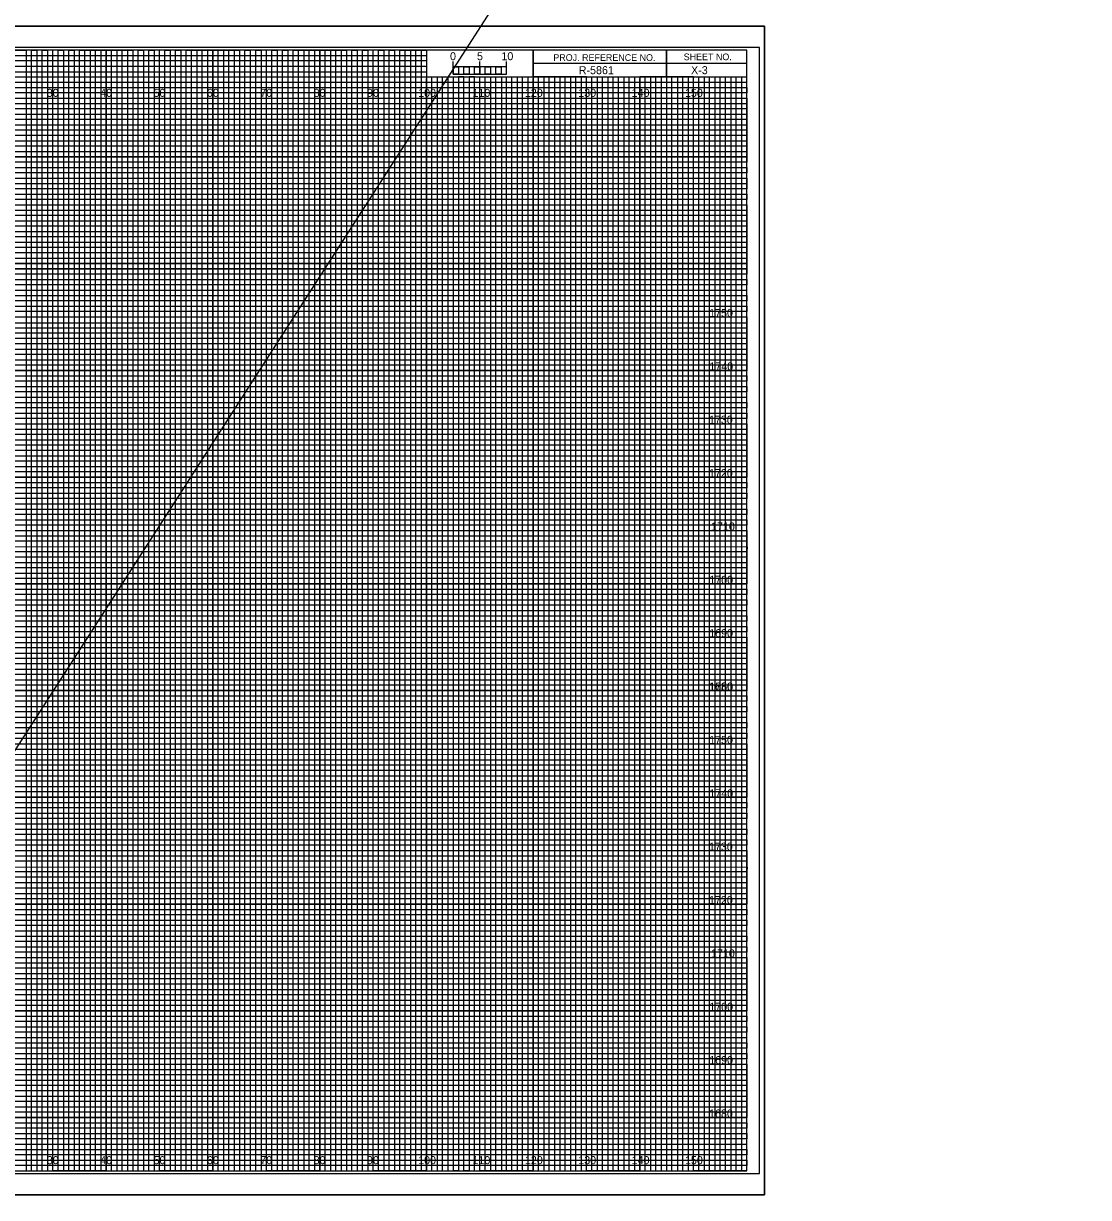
# Model space of a CAD drawing. Extents: x -419 to 4739, y -630 to 13534.
# Drawn here: x 184.5 to 384, y 435 to 655 of the extents above; entities that cross this region are included whole.
import ezdxf

# ---------------------------------------------------------------- set-up
doc = ezdxf.new("R2010")
doc.units = 0
for name, color, linetype in [('Old_Level_1', 7, 'Continuous'), ('Old_Level_62', 7, 'Continuous'), ('Pattern 1', 7, 'Continuous'), ('Pattern 18', 7, 'Continuous'), ('Pattern 4', 7, 'Continuous'), ('Pattern 5', 7, 'Continuous'), ('Prop Dimension', 7, 'Continuous'), ('Prop Horizontal Alignment', 7, 'Continuous'), ('Prop PHM Label Text', 7, 'Continuous'), ('Prop PHM Label Text White', 7, 'Continuous'), ('Prop PHM Roadway Shape', 7, 'Continuous'), ('Raster_Level_0', 7, 'Continuous'), ('Scratch_Level_0', 7, 'Continuous'), ('Scratch_Level_3', 7, 'Continuous'), ('Scratch_Level_5', 7, 'Continuous')]:
    doc.layers.add(name, color=color, linetype=linetype)

msp = doc.modelspace()

# ---------------------------------------------------------------- linework, layer by layer
at = {"layer": 'Old_Level_62'}
for p, q in [((305, 650), (305, 645)), ((305, 645), (305, 650)), ((280, 647.5), (280, 645)), ((320, 647.49), (280, 647.49)), ((280, 645), (320, 645))]:
    msp.add_line(p, q, dxfattribs=at)
for points in [[(320, 650), (0, 650), (0, 440), (320, 440)], [(280, 650), (260, 650), (260, 645.03), (280, 645.03)], [(320, 650), (280, 650), (280, 645), (320, 645)]]:
    msp.add_lwpolyline(points, close=True, dxfattribs=at)
at = {"layer": 'Pattern 18'}
msp.add_line((-419.01, -416.83), (1573.75, 2680.65), dxfattribs=at)
for points in [[(-13.4, 435.5), (323.3, 435.5), (323.3, 654.5), (-13.4, 654.5)], [(-13.4, 654.5), (323.3, 654.5), (323.3, 435.5), (-13.4, 435.5)]]:
    msp.add_lwpolyline(points, close=True, dxfattribs=at)
at = {"layer": 'Pattern 4'}
for p, q in [((0, 649), (260, 649)), ((260, 649), (260, 647.98)), ((260, 647.98), (0, 647.98)), ((0, 647), (260, 647)), ((260, 647), (260, 645.89)), ((260, 645.89), (0, 645.89)), ((0, 644), (320, 644))]:
    msp.add_line(p, q, dxfattribs=at)
for points in [[(0, 643), (270, 643), (320, 643), (320, 642), (0, 642)], [(0, 641), (320, 641), (320, 639), (0, 639)], [(0, 638), (320, 638), (320, 637), (0, 636.98)], [(0, 636), (320, 636), (320, 634), (0, 634)], [(0, 633), (320, 633), (320, 632), (0, 632)], [(0, 631), (320, 631), (320, 629), (0, 629)], [(0, 628), (320, 628), (320, 627), (0, 627)], [(0, 626), (320, 626), (320, 624), (0, 624)], [(0, 623), (320, 623), (320, 622), (0, 622)], [(0, 621), (320, 621), (320, 619), (0, 619)], [(0, 618), (320, 618), (320, 617), (0, 617)], [(0, 616), (320, 616), (320, 613.95), (320, 613), (320, 612), (0, 612)], [(0, 614), (320, 614), (320, 613), (0, 613)], [(0, 611), (320, 611), (320, 609), (0, 609.03)], [(0, 609.03), (320, 609), (320, 608), (0, 608)], [(0, 607), (320, 607), (320, 606), (0, 606)], [(0, 604), (320, 604), (320, 603), (0, 603)], [(0, 602), (320, 602), (320, 601), (0, 601)], [(-0.07, 598.89), (320, 598.89), (320, 597.88), (-0.07, 597.88)], [(0, 597), (320, 597), (320, 596), (0, 596)], [(0, 594), (320, 594), (320, 593), (0, 593)], [(0, 592), (320, 592), (320, 591), (0, 591)], [(0, 589), (320, 589), (320, 588), (0, 588)], [(0, 587), (320, 587), (320, 586), (0, 586)], [(0, 584), (320, 584), (320, 583), (0, 583)], [(0, 582), (320, 582), (320, 581), (0, 581)], [(0, 579), (320, 579), (319.99, 577.98), (0, 578)], [(0, 577), (320, 577), (320, 576), (0, 576)], [(0, 574), (320, 574), (320, 573), (0, 573)], [(0, 572), (320, 572), (320, 571), (0, 571)], [(0, 569), (320, 569), (320, 568), (0, 568)], [(0, 567), (320, 567), (320, 566), (0, 566)], [(0, 564), (320, 564), (320, 563), (0, 563)], [(0, 562), (320, 562), (320, 561), (0, 561)], [(0, 559), (320, 559), (320, 558), (0, 558)], [(0, 556.99), (320.07, 556.91), (320, 556), (0, 556)], [(0, 554), (320, 554), (320, 553), (0, 553)], [(0, 552), (320, 552), (320, 551), (0, 551)], [(0, 549), (320, 549), (320, 548), (0, 548)], [(0, 547), (320, 547), (320, 546), (0, 546)], [(0, 544), (320, 544), (320, 543), (0, 543)], [(0, 542), (320, 542), (320, 541), (0, 541)], [(0, 539), (320, 539), (320, 538), (0, 538)], [(0, 537), (320, 537), (320, 536), (0, 536)], [(0, 534), (320, 534), (320, 533), (0, 533)], [(0, 532), (320, 532), (320, 531), (0, 531)], [(0, 529), (320, 529), (320, 528), (0, 528)], [(0, 527), (320, 527), (320, 526), (0, 526)], [(0, 524), (320, 524), (320, 523), (0, 523)], [(0, 522), (320, 522), (320, 521), (0, 521)], [(0, 519), (320, 519), (319.99, 517.98), (0, 518)], [(0, 517), (320, 517), (320, 516), (0, 516)], [(0, 514), (320, 514), (320, 513), (0, 513)], [(0, 512), (320, 512), (320, 511), (0, 511)], [(0, 509), (320, 509), (320, 508), (0, 508)], [(0, 507), (320, 507), (320, 506), (0, 506)], [(0, 504), (320, 504), (320, 503), (0, 503)], [(0, 502), (320, 502), (320, 501), (0, 501)], [(0, 499), (320, 499), (320, 498), (0, 498)], [(0, 496.99), (320.07, 496.91), (320, 496), (0, 496)], [(0, 494), (320, 494), (320, 493), (0, 493)], [(0, 492), (320, 492), (320, 491), (0, 491)], [(0, 489), (320, 489), (320, 488), (0, 488)], [(0, 487), (320, 487), (320, 486), (0, 486)], [(0, 484), (320, 484), (320, 483), (0, 483)], [(0, 482), (320, 482), (320, 481), (0, 481)], [(0, 479), (320, 479), (320, 478), (0, 478)], [(0, 477), (320, 477), (320, 476), (0, 476)], [(0, 474), (320, 474), (320, 473), (0, 473)], [(0, 472), (320, 472), (320, 471), (0, 471)], [(0, 469), (320, 469), (320, 468), (0, 468)], [(0, 467), (320, 467), (320, 466), (0, 466)], [(0, 464), (320, 464), (320, 463), (0, 463)], [(0, 462), (320, 462), (320, 461), (0, 461)], [(0, 459), (320, 459), (320, 458), (0, 458)], [(0, 457), (320, 457), (320, 456), (0, 456)], [(0, 454), (320, 454), (320, 453), (0, 453)], [(0, 452), (320, 452), (320, 451), (0, 451)], [(0, 449), (320, 449), (320, 448), (0, 448)], [(0, 447), (320, 447), (320, 446), (0, 446)], [(0, 444), (320, 444), (320, 443), (0, 443)], [(0, 442), (320, 442), (320, 441), (0, 441)]]:
    msp.add_lwpolyline(points, dxfattribs=at)
at = {"layer": 'Pattern 5'}
for p, q in [((323.3, 654.5), (-13.4, 654.5)), ((-13.4, 435.5), (323.3, 435.5))]:
    msp.add_line(p, q, dxfattribs=at)
at = {"layer": 'Prop Dimension'}
for p, q in [((267, 645), (266.01, 645)), ((266.01, 645), (266.01, 440)), ((267, 440), (267, 645)), ((269, 645), (268, 645)), ((268, 645), (268, 440)), ((269, 440), (269, 645)), ((266.01, 440), (265, 440)), ((268, 440), (267, 440))]:
    msp.add_line(p, q, dxfattribs=at)
for points in [[(185, 440), (186, 440), (186, 650), (187, 650), (187, 440)], [(187, 440), (188, 440), (188, 650), (189, 650), (189, 440)], [(190, 440), (191, 440), (191, 650), (192, 650), (192, 440)], [(192, 440), (193, 440), (193, 650), (194, 650), (194, 440)], [(195, 440), (196, 440), (196, 650), (197, 650), (197, 440)], [(197, 440), (198, 440), (198, 650), (199, 650), (199, 440)], [(200, 440), (201, 440), (201, 650), (202, 650), (202, 440)], [(202, 440), (203, 440), (203, 650), (204, 650), (204, 440)], [(205, 440), (206, 440), (206, 650), (207, 650), (207, 440)], [(207, 440), (208, 440), (208, 650), (209, 650), (209, 440)], [(210, 440), (211, 440), (211, 650), (212, 650), (212, 440)], [(212, 440), (213, 440), (213, 650), (214, 650), (214, 440)], [(215, 440), (216, 440), (216, 650), (217, 650), (217, 440)], [(217, 440), (218, 440), (218, 650), (219, 650), (219, 440)], [(220, 440), (221, 440), (221, 650), (222, 650), (222, 440)], [(222, 440), (223, 440), (223, 650), (224, 650), (224, 440)], [(225, 440), (226, 440), (226, 650), (227, 650), (227, 440)], [(227, 440), (228, 440), (228, 650), (229, 650), (229, 440)], [(230, 440), (231, 440), (231, 650), (232, 650), (232, 440)], [(232, 440), (233, 440), (233, 650), (234, 650), (234, 440)], [(235, 440), (236, 440), (236, 650), (237, 650), (237, 440)], [(237, 440), (238, 440), (238, 650), (239, 650), (239, 440)], [(240, 440), (241, 440), (241, 650), (242, 650), (242, 440)], [(242, 440), (243, 440), (243, 650), (244, 650), (244, 440)], [(245, 440), (246, 440), (246, 650), (247, 650), (247, 440)], [(247, 440), (248, 440), (248, 650), (249, 650), (249, 440)], [(250, 440), (251, 440), (251, 650), (252, 650), (252, 440)], [(252, 440), (253, 440), (253, 650), (254, 650), (254, 440)], [(255, 440), (256, 440), (256, 650), (257, 650), (257, 440)], [(257, 440), (258, 440), (258, 650), (259, 650), (259, 440)], [(260, 440), (261, 440), (261, 645), (262.02, 645), (262.02, 440)], [(262, 440), (263, 440), (263, 645), (263.99, 645), (263.99, 440)], [(270, 440), (270.98, 440), (270.98, 645), (272, 645), (272, 440)], [(272, 440), (273, 440), (273, 645), (274.05, 645), (274.05, 440)], [(275, 440), (276, 440), (276, 645), (277, 645), (277, 440)], [(277, 440), (278, 440), (278, 645), (279, 645), (279, 440)], [(280, 440), (281, 440), (281, 645), (282, 645), (282, 440)], [(282, 440), (283, 440), (283, 645), (284, 645), (284, 440)], [(285, 440), (286, 440), (286, 645), (287, 645), (287, 440)], [(287, 440), (288, 440), (288, 645), (289, 645), (289, 440)], [(290, 440), (291, 440), (291, 645), (292, 645), (292, 440)], [(292, 440), (293, 440), (293, 645), (294, 645), (294, 440)], [(295, 440), (296, 440), (296, 645), (297, 645), (297, 440)], [(297, 440), (298, 440), (298, 645), (299, 645), (299, 440)], [(300, 440), (301, 440), (301, 645), (302, 645), (302, 440)], [(302, 440), (303, 440), (303, 645), (304, 645), (304, 440)], [(305, 440), (306, 440), (306, 645), (307, 645), (307, 440)], [(307, 440), (308, 440), (308, 645), (309, 645), (309, 440)], [(310, 440), (311, 440), (311, 645), (312, 645), (312, 440)], [(312, 440), (313, 440), (313, 645), (314, 645), (314, 440)], [(315, 440), (316, 440), (316, 645), (317, 645), (317, 440)], [(317, 440), (318, 440), (318, 645), (319, 645), (319, 440)]]:
    msp.add_lwpolyline(points, dxfattribs=at)
at = {"layer": 'Prop Horizontal Alignment'}
for points in [[(175, 650), (185, 650), (185, 440), (195, 440), (195, 650), (205, 650), (205, 440), (215, 440), (215, 650), (225, 650), (225, 440), (235, 440), (235, 650), (245, 650), (245, 440), (255, 440), (255, 650), (259.93, 650), (260, 650), (260, 645), (264.99, 645), (264.99, 440), (275, 440), (275, 645), (285, 645), (285, 440), (295, 440), (295, 645), (305, 645), (305, 440), (315, 440), (315, 645)], [(0, 645), (275, 645)], [(0, 625), (320, 625), (320, 635), (0, 635)], [(0, 605), (320, 605), (320, 615), (0, 615)], [(0, 585), (320, 585), (320, 595), (0, 595)], [(0, 565), (320, 565), (320, 575), (0, 575)], [(0, 545), (320, 545), (320, 555), (0, 555)], [(0, 525), (320, 525), (320, 535), (0, 535)], [(0, 505), (320, 505), (320, 515), (0, 515)], [(0, 485), (320, 485), (320, 495), (0, 495)], [(0, 465), (320, 465), (320, 475), (0, 475)], [(0, 445), (320, 445), (320, 455), (0, 455)]]:
    msp.add_lwpolyline(points, dxfattribs=at)
at = {"layer": 'Prop PHM Label Text'}
for p, q in [((265, 645.49), (265, 647.9)), ((265, 646.9), (265, 647.9)), ((270, 645.49), (270, 647.9)), ((275, 645.49), (275, 647.9)), ((275, 646.9), (275, 647.9))]:
    msp.add_line(p, q, dxfattribs=at)
for points in [[(275, 646.9), (265, 646.9), (265, 645.49), (275, 645.49)], [(265, 646.9), (266, 646.9), (266, 645.49), (265, 645.49)], [(267, 646.9), (268, 646.9), (268, 645.49), (267, 645.49)], [(269, 646.9), (270, 646.9), (270, 645.49), (269, 645.49)], [(271, 646.9), (272, 646.9), (272, 645.49), (271, 645.49)], [(273, 646.9), (274, 646.9), (274, 645.49), (273, 645.49)]]:
    msp.add_lwpolyline(points, close=True, dxfattribs=at)
at = {"layer": 'Scratch_Level_0'}
for p, q in [((190, 440), (190, 650)), ((200, 440), (200, 650)), ((210, 440), (210, 650)), ((220, 440), (220, 650)), ((230, 440), (230, 650)), ((240, 440), (240, 650)), ((250, 440), (250, 650)), ((260, 440), (260, 644.69)), ((270, 440), (270, 644.69)), ((280, 440), (280, 644.69)), ((290, 440), (290, 644.69)), ((300, 440), (300, 644.69)), ((310, 440), (310, 644.69)), ((0, 640), (320, 640)), ((0, 630), (320, 630)), ((0, 620), (320, 620)), ((0, 610), (320, 610)), ((0, 600), (320, 600)), ((0, 590), (320, 590)), ((0, 580), (320, 580)), ((0, 570), (320, 570)), ((0, 560), (320, 560)), ((0, 550), (320, 550)), ((0, 540), (320, 540)), ((0, 530), (320, 530)), ((0, 520), (320, 520)), ((0, 510), (320, 510)), ((0, 500), (320, 500)), ((0, 490), (320, 490)), ((0, 480), (320, 480)), ((0, 470), (320, 470)), ((0, 460), (320, 460)), ((0, 450), (320, 450))]:
    msp.add_line(p, q, dxfattribs=at)
at = {"layer": 'Scratch_Level_3'}
for p, q in [((190, 650), (180, 650)), ((190, 440), (190, 650)), ((210, 650), (200, 650)), ((200, 650), (200, 440)), ((210, 440), (210, 650)), ((230, 650), (220, 650)), ((220, 650), (220, 440)), ((230, 440), (230, 650)), ((250, 650), (240, 650)), ((240, 650), (240, 440)), ((250, 440), (250, 650)), ((260, 650), (260, 440)), ((270, 440), (270, 645)), ((290, 645), (280, 645)), ((280, 645), (280, 440)), ((290, 440), (290, 645)), ((310, 645), (300, 645)), ((300, 645), (300, 440)), ((310, 440), (310, 645)), ((200, 440), (190, 440)), ((220, 440), (210, 440)), ((240, 440), (230, 440)), ((260, 440), (250, 440)), ((280, 440), (270, 440)), ((300, 440), (290, 440)), ((320, 440), (310, 440)), ((320, 440), (320, 440))]:
    msp.add_line(p, q, dxfattribs=at)
for points in [[(0, 640), (320, 640), (320, 630), (0, 630)], [(0, 620), (320, 620), (320, 610), (0, 610)], [(0, 600), (320, 600), (320, 590), (0, 590)], [(0, 580), (320, 580), (320, 570), (0, 570)], [(0, 560), (320, 560), (320, 550), (0, 550)], [(0, 540), (320, 540), (320, 530), (0, 530)], [(0, 520), (320, 520), (320, 510), (0, 510)], [(0, 500), (320, 500), (320, 490), (0, 490)], [(0, 480), (320, 480), (320, 470), (0, 470)], [(0, 460), (320, 460), (320, 450), (0, 450)]]:
    msp.add_lwpolyline(points, dxfattribs=at)
at = {"layer": 'Scratch_Level_5'}
msp.add_lwpolyline([(-10.8, 439.5), (322.4, 439.5), (322.4, 650.5), (-10.8, 650.5)], close=True, dxfattribs=at)

# ---------------------------------------------------------------- texts
at = {"layer": 'Old_Level_1'}
for s, p in [('5', (269.47, 648.12)), ('10', (274.04, 648.12))]:
    msp.add_text(s, height=1.5, dxfattribs=at).set_placement(p)
at = {"layer": 'Old_Level_62'}
for s, p in [('PROJ. REFERENCE NO.', (283.77, 647.99)), ('SHEET NO.', (308.19, 648.12))]:
    msp.add_text(s, height=1.25, dxfattribs=at).set_placement(p)
at = {"layer": 'Pattern 1'}
for s, p in [('1750', (312.96, 600)), ('1740', (313, 590)), ('1730', (312.92, 580)), ('1720', (312.93, 570)), ('1710', (313.31, 560)), ('1700', (312.98, 550)), ('1690', (312.97, 540)), ('1680', (312.95, 530)), ('1760', (313, 530)), ('1750', (312.96, 520)), ('1740', (313, 510)), ('1730', (312.92, 500)), ('1720', (312.93, 490)), ('1710', (313.31, 480)), ('1700', (312.98, 470)), ('1690', (312.97, 460)), ('1680', (312.95, 450))]:
    msp.add_text(s, height=1.5, dxfattribs=at).set_placement(p)
at = {"layer": 'Prop PHM Label Text'}
msp.add_text('0', height=1.5, dxfattribs=at).set_placement((264.41, 648.12))
at = {"layer": 'Prop PHM Label Text White'}
msp.add_text('X-3', height=1.5, dxfattribs=at).set_placement((309.57, 645.5))
at = {"layer": 'Prop PHM Roadway Shape'}
msp.add_text('R-5861', height=1.5, dxfattribs=at).set_placement((288.53, 645.5))
at = {"layer": 'Raster_Level_0'}
for s, p in [('30', (188.86, 641.25)), ('40', (198.86, 641.25)), ('50', (208.86, 641.25)), ('60', (218.86, 641.25)), ('70', (228.86, 641.25)), ('80', (238.86, 641.25)), ('90', (248.86, 641.25)), ('100', (258.44, 641.25)), ('110', (268.62, 641.25)), ('120', (278.44, 641.25)), ('130', (288.44, 641.25)), ('140', (298.44, 641.25)), ('150', (308.44, 641.25)), ('30', (188.86, 441.25)), ('40', (198.86, 441.25)), ('50', (208.86, 441.25)), ('60', (218.86, 441.25)), ('70', (228.86, 441.25)), ('80', (238.86, 441.25)), ('90', (248.86, 441.25)), ('100', (258.44, 441.25)), ('110', (268.62, 441.25)), ('120', (278.44, 441.25)), ('130', (288.44, 441.25)), ('140', (298.44, 441.25)), ('150', (308.44, 441.25))]:
    msp.add_text(s, height=1.5, dxfattribs=at).set_placement(p)

doc.saveas('drawing.dxf')
